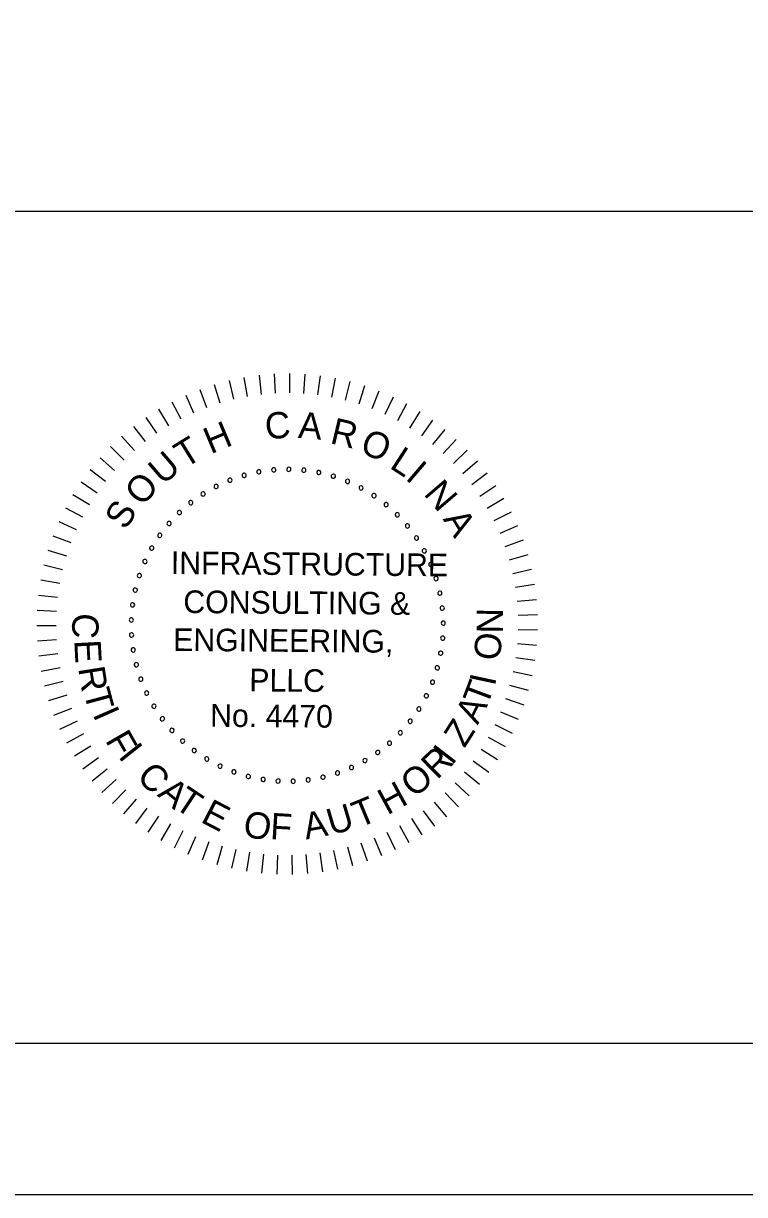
# Model space of a CAD drawing. Extents: x -133.1 to -97, y -1.7 to 20.6.
# Drawn here: x -107.68 to -105.296, y -1.691 to 2.18 of the extents above; entities that cross this region are included whole.
import ezdxf

# ---------------------------------------------------------------- set-up
doc = ezdxf.new("R2010")
doc.units = 0
for name, color, linetype in [('BR_BORDER LINES', 7, 'Continuous'), ('BR_TEXT', 7, 'Continuous'), ('Level 31', 7, 'Continuous')]:
    doc.layers.add(name, color=color, linetype=linetype)

msp = doc.modelspace()

# ---------------------------------------------------------------- linework, layer by layer
at = {"layer": 'BR_BORDER LINES'}
for p, q in [((-110.5071, 1.5591), (-105.1419, 1.5591)), ((-131.3076, -1.191), (-97.6416, -1.191))]:
    msp.add_line(p, q, dxfattribs=at)
at = {"layer": 'BR_TEXT'}
for p, q in [((-106.9512, 1.01), (-106.9401, 0.9473)), ((-106.9012, 1.0172), (-106.894, 0.9539)), ((-106.8509, 1.0213), (-106.8476, 0.9578)), ((-106.8005, 1.0224), (-106.801, 0.9587)), ((-106.75, 1.0204), (-106.7544, 0.9569)), ((-106.6998, 1.0153), (-106.7081, 0.9522)), ((-106.65, 1.0071), (-106.6621, 0.9446)), ((-107.0972, 0.9704), (-107.0749, 0.9107)), ((-107.0494, 0.9866), (-107.0308, 0.9257)), ((-107.0007, 0.9998), (-106.9858, 0.9379)), ((-106.6007, 0.996), (-106.6166, 0.9343)), ((-106.5523, 0.9818), (-106.5719, 0.9213)), ((-107.1895, 0.9295), (-107.1601, 0.873)), ((-107.1439, 0.9513), (-107.1181, 0.8932)), ((-106.5048, 0.9648), (-106.528, 0.9055)), ((-106.4584, 0.9448), (-106.4852, 0.8871)), ((-107.2335, 0.9049), (-107.2008, 0.8503)), ((-106.4133, 0.9221), (-106.4436, 0.8661)), ((-106.3697, 0.8967), (-106.4034, 0.8426)), ((-107.276, 0.8776), (-107.24, 0.8251)), ((-106.3277, 0.8686), (-106.3646, 0.8167)), ((-107.3557, 0.8156), (-107.3135, 0.7679)), ((-107.3168, 0.8478), (-107.2776, 0.7976)), ((-106.2875, 0.8381), (-106.3275, 0.7885)), ((-107.3925, 0.7811), (-107.3475, 0.736)), ((-106.2493, 0.8051), (-106.2922, 0.7581)), ((-107.4272, 0.7444), (-107.3795, 0.7022)), ((-106.2131, 0.7699), (-106.2588, 0.7256)), ((-107.4595, 0.7056), (-107.4094, 0.6664)), ((-106.1791, 0.7326), (-106.2275, 0.6911)), ((-107.4895, 0.665), (-107.437, 0.6289)), ((-106.1475, 0.6932), (-106.1983, 0.6548)), ((-107.5169, 0.6226), (-107.4623, 0.5897)), ((-106.1184, 0.652), (-106.1714, 0.6167)), ((-106.0918, 0.6091), (-106.1469, 0.5771)), ((-107.5416, 0.5786), (-107.4852, 0.5491)), ((-106.0679, 0.5646), (-106.1248, 0.5361)), ((-107.5637, 0.5332), (-107.5055, 0.5072)), ((-106.0467, 0.5188), (-106.1052, 0.4938)), ((-107.5829, 0.4865), (-107.5233, 0.4641)), ((-106.0283, 0.4718), (-106.0883, 0.4504)), ((-107.5992, 0.4387), (-107.5384, 0.42)), ((-107.6126, 0.3901), (-107.5507, 0.3751)), ((-106.0129, 0.4237), (-106.0741, 0.406)), ((-106.0004, 0.3748), (-106.0625, 0.3608)), ((-107.623, 0.3407), (-107.5604, 0.3295)), ((-105.9909, 0.3252), (-106.0538, 0.3151)), ((-107.6304, 0.2907), (-107.5672, 0.2834)), ((-105.9845, 0.2751), (-106.0479, 0.2689)), ((-107.6348, 0.2404), (-107.5712, 0.237)), ((-105.9811, 0.2247), (-106.0448, 0.2224)), ((-107.636, 0.19), (-107.5723, 0.1904)), ((-105.9809, 0.1743), (-106.0445, 0.1758)), ((-107.6342, 0.1395), (-107.5706, 0.1438)), ((-105.9836, 0.1239), (-106.0471, 0.1292)), ((-107.6293, 0.0893), (-107.5661, 0.0974)), ((-105.9895, 0.0737), (-106.0525, 0.0829)), ((-107.6213, 0.0394), (-107.5588, 0.0514)), ((-107.6103, -0.0099), (-107.5487, 0.0059)), ((-105.9984, 0.024), (-106.0607, 0.0371)), ((-106.0103, -0.025), (-106.0717, -0.0082)), ((-107.5964, -0.0584), (-107.5358, -0.0388)), ((-106.0252, -0.0733), (-106.0855, -0.0527)), ((-107.5795, -0.106), (-107.5202, -0.0828)), ((-106.043, -0.1205), (-106.1019, -0.0963)), ((-107.5597, -0.1524), (-107.5019, -0.1256)), ((-106.0636, -0.1666), (-106.1209, -0.1389)), ((-107.5371, -0.1976), (-107.4811, -0.1673)), ((-106.087, -0.2113), (-106.1426, -0.1802)), ((-107.5119, -0.2413), (-107.4578, -0.2077)), ((-106.1131, -0.2545), (-106.1667, -0.22)), ((-107.484, -0.2834), (-107.4321, -0.2465)), ((-106.1418, -0.2961), (-106.1931, -0.2584)), ((-107.4536, -0.3237), (-107.404, -0.2837)), ((-106.173, -0.3358), (-106.2219, -0.2951)), ((-107.4208, -0.362), (-107.3737, -0.3191)), ((-106.2065, -0.3735), (-106.2529, -0.3299)), ((-107.3857, -0.3983), (-107.3413, -0.3527)), ((-107.3485, -0.4324), (-107.307, -0.3841)), ((-106.2423, -0.4092), (-106.2859, -0.3628)), ((-107.3092, -0.4642), (-107.2708, -0.4135)), ((-106.32, -0.4736), (-106.3576, -0.4222)), ((-106.2801, -0.4426), (-106.3208, -0.3936)), ((-107.2681, -0.4935), (-107.2328, -0.4405)), ((-106.3616, -0.5021), (-106.3961, -0.4485)), ((-107.2253, -0.5203), (-107.1933, -0.4652)), ((-107.1809, -0.5444), (-107.1523, -0.4875)), ((-106.4498, -0.5513), (-106.4774, -0.4939)), ((-106.4049, -0.528), (-106.436, -0.4725)), ((-107.1352, -0.5657), (-107.1101, -0.5072)), ((-107.0882, -0.5842), (-107.0668, -0.5243)), ((-107.0402, -0.5998), (-107.0225, -0.5387)), ((-106.5432, -0.5894), (-106.5637, -0.5291)), ((-106.4959, -0.5718), (-106.52, -0.5128)), ((-106.9913, -0.6125), (-106.9773, -0.5504)), ((-106.9418, -0.6221), (-106.9316, -0.5593)), ((-106.8918, -0.6288), (-106.8854, -0.5654)), ((-106.8414, -0.6323), (-106.8389, -0.5687)), ((-106.7909, -0.6328), (-106.7923, -0.5691)), ((-106.7405, -0.6302), (-106.7458, -0.5667)), ((-106.6903, -0.6245), (-106.6995, -0.5615)), ((-106.6406, -0.6158), (-106.6536, -0.5535)), ((-106.5915, -0.6041), (-106.6083, -0.5427))]:
    msp.add_line(p, q, dxfattribs=at)
for centre, start, end in [((-106.9021, 0.6977), 10.6038, 190.6038), ((-106.9021, 0.6977), 190.6038, 10.6038), ((-106.8527, 0.7043), 5.0653, 185.0653), ((-106.8527, 0.7043), 185.0653, 5.0653), ((-106.8029, 0.7062), 359.5268, 179.5268), ((-106.8029, 0.7062), 179.5268, 359.5268), ((-106.7531, 0.7033), 173.9884, 353.9884), ((-106.7531, 0.7033), 353.9884, 173.9884), ((-106.7039, 0.6956), 168.4499, 348.4499), ((-106.7039, 0.6956), 348.4499, 168.4499), ((-106.9977, 0.6702), 21.6807, 201.6807), ((-106.9977, 0.6702), 201.6807, 21.6807), ((-106.9506, 0.6862), 16.1422, 196.1422), ((-106.9506, 0.6862), 196.1422, 16.1422), ((-106.6557, 0.6832), 162.9114, 342.9114), ((-106.6557, 0.6832), 342.9114, 162.9114), ((-106.6088, 0.6662), 157.373, 337.373), ((-106.6088, 0.6662), 337.373, 157.373), ((-107.0864, 0.6248), 32.7576, 212.7576), ((-107.0864, 0.6248), 212.7576, 32.7576), ((-107.0431, 0.6496), 27.2191, 207.2191), ((-107.0431, 0.6496), 207.2191, 27.2191), ((-106.5639, 0.6447), 151.8345, 331.8345), ((-106.5639, 0.6447), 331.8345, 151.8345), ((-106.5212, 0.619), 146.2961, 326.2961), ((-106.5212, 0.619), 326.2961, 146.2961), ((-107.127, 0.5959), 38.2961, 218.2961), ((-107.127, 0.5959), 218.2961, 38.2961), ((-106.4811, 0.5893), 140.7576, 320.7576), ((-106.4811, 0.5893), 320.7576, 140.7576), ((-107.1646, 0.5633), 43.8345, 223.8345), ((-107.1646, 0.5633), 223.8345, 43.8345), ((-106.4442, 0.5559), 135.2191, 315.2191), ((-106.4442, 0.5559), 315.2191, 135.2191), ((-107.1989, 0.5271), 49.373, 229.373), ((-107.1989, 0.5271), 229.373, 49.373), ((-106.4106, 0.5191), 129.6807, 309.6807), ((-106.4106, 0.5191), 309.6807, 129.6807), ((-107.2296, 0.4879), 54.9114, 234.9114), ((-107.2296, 0.4879), 234.9114, 54.9114), ((-106.3808, 0.4792), 124.1422, 304.1422), ((-106.3808, 0.4792), 304.1422, 124.1422), ((-107.2563, 0.4458), 60.4499, 240.4499), ((-107.2563, 0.4458), 240.4499, 60.4499), ((-106.3549, 0.4366), 118.6038, 298.6038), ((-106.3549, 0.4366), 298.6038, 118.6038), ((-107.2788, 0.4014), 65.9884, 245.9884), ((-107.2788, 0.4014), 245.9884, 65.9884), ((-106.3333, 0.3917), 113.0653, 293.0653), ((-106.3333, 0.3917), 293.0653, 113.0653), ((-107.297, 0.3549), 71.5268, 251.5268), ((-107.297, 0.3549), 251.5268, 71.5268), ((-106.3161, 0.3449), 107.5268, 287.5268), ((-106.3161, 0.3449), 287.5268, 107.5268), ((-107.3106, 0.307), 77.0653, 257.0653), ((-107.3106, 0.307), 257.0653, 77.0653), ((-106.3035, 0.2967), 101.9884, 281.9884), ((-106.3035, 0.2967), 281.9884, 101.9884), ((-107.3195, 0.258), 82.6038, 262.6038), ((-107.3195, 0.258), 262.6038, 82.6038), ((-106.2956, 0.2475), 96.4499, 276.4499), ((-106.2956, 0.2475), 276.4499, 96.4499), ((-107.3236, 0.2083), 88.1422, 268.1422), ((-107.3236, 0.2083), 268.1422, 88.1422), ((-106.2925, 0.1977), 90.9114, 270.9114), ((-106.2925, 0.1977), 270.9114, 90.9114), ((-107.3229, 0.1585), 93.6807, 273.6807), ((-107.3229, 0.1585), 273.6807, 93.6807), ((-106.2942, 0.1479), 85.373, 265.373), ((-106.2942, 0.1479), 265.373, 85.373), ((-107.3174, 0.109), 99.2191, 279.2191), ((-107.3174, 0.109), 279.2191, 99.2191), ((-106.3007, 0.0985), 79.8345, 259.8345), ((-106.3007, 0.0985), 259.8345, 79.8345), ((-107.3071, 0.0602), 104.7576, 284.7576), ((-107.3071, 0.0602), 284.7576, 104.7576), ((-106.312, 0.05), 74.2961, 254.2961), ((-106.312, 0.05), 254.2961, 74.2961), ((-107.2922, 0.0126), 110.2961, 290.2961), ((-107.2922, 0.0126), 290.2961, 110.2961), ((-106.3279, 0.0028), 68.7576, 248.7576), ((-106.3279, 0.0028), 248.7576, 68.7576), ((-107.2728, -0.0332), 115.8345, 295.8345), ((-107.2728, -0.0332), 295.8345, 115.8345), ((-106.3483, -0.0427), 63.2191, 243.2191), ((-106.3483, -0.0427), 243.2191, 63.2191), ((-107.249, -0.077), 121.373, 301.373), ((-107.249, -0.077), 301.373, 121.373), ((-107.2211, -0.1183), 126.9114, 306.9114), ((-107.2211, -0.1183), 306.9114, 126.9114), ((-106.3729, -0.086), 57.6807, 237.6807), ((-106.3729, -0.086), 237.6807, 57.6807), ((-107.1894, -0.1567), 132.4499, 312.4499), ((-107.1894, -0.1567), 312.4499, 132.4499), ((-106.4016, -0.1267), 52.1422, 232.1422), ((-106.4016, -0.1267), 232.1422, 52.1422), ((-107.1541, -0.1919), 137.9884, 317.9884), ((-107.1541, -0.1919), 317.9884, 137.9884), ((-106.4702, -0.1989), 41.0653, 221.0653), ((-106.4342, -0.1645), 46.6038, 226.6038), ((-106.4342, -0.1645), 226.6038, 46.6038), ((-107.1156, -0.2235), 143.5268, 323.5268), ((-107.1156, -0.2235), 323.5268, 143.5268), ((-106.5093, -0.2297), 35.5268, 215.5268), ((-106.5093, -0.2297), 215.5268, 35.5268), ((-106.4702, -0.1989), 221.0653, 41.0653), ((-107.0742, -0.2512), 149.0653, 329.0653), ((-107.0742, -0.2512), 329.0653, 149.0653), ((-107.0303, -0.2749), 334.6038, 154.6038), ((-106.5513, -0.2566), 29.9884, 209.9884), ((-106.5513, -0.2566), 209.9884, 29.9884), ((-107.0303, -0.2749), 154.6038, 334.6038), ((-106.9843, -0.2941), 160.1422, 340.1422), ((-106.9843, -0.2941), 340.1422, 160.1422), ((-106.9367, -0.3089), 165.6807, 345.6807), ((-106.9367, -0.3089), 345.6807, 165.6807), ((-106.6899, -0.3114), 13.373, 193.373), ((-106.642, -0.2976), 18.9114, 198.9114), ((-106.642, -0.2976), 198.9114, 18.9114), ((-106.5957, -0.2793), 24.4499, 204.4499), ((-106.5957, -0.2793), 204.4499, 24.4499), ((-106.8879, -0.3189), 171.2191, 351.2191), ((-106.8879, -0.3189), 351.2191, 171.2191), ((-106.8384, -0.3242), 356.7576, 176.7576), ((-106.8384, -0.3242), 176.7576, 356.7576), ((-106.7885, -0.3248), 2.2961, 182.2961), ((-106.7885, -0.3248), 182.2961, 2.2961), ((-106.7389, -0.3205), 7.8345, 187.8345), ((-106.7389, -0.3205), 187.8345, 7.8345), ((-106.6899, -0.3114), 193.373, 13.373)]:
    msp.add_arc(centre, 0.00701, start, end, dxfattribs=at)
at = {"layer": 'Level 31'}
msp.add_lwpolyline([(-133.1409, -1.691), (-97.141, -1.691), (-97.141, 20.309), (-133.1409, 20.309)], close=True, dxfattribs=at)

# ---------------------------------------------------------------- texts
at = {"layer": 'BR_TEXT'}
for s, height, rotation, p in [('C', 0.0872, 4.7281, (-106.8784, 0.8048)), ('A', 0.0872, 355.6981, (-106.7739, 0.8098)), ('H', 0.0872, 22.7882, (-107.0612, 0.7554)), ('R', 0.0872, 346.6681, (-106.6696, 0.7928)), ('T', 0.0872, 31.8182, (-107.1461, 0.7078)), ('O', 0.0872, 337.638, (-106.5719, 0.763)), ('L', 0.0872, 327.108, (-106.4731, 0.7125)), ('U', 0.0872, 40.8482, (-107.2194, 0.6516)), ('I', 0.0872, 319.578, (-106.4205, 0.6747)), ('O', 0.0872, 49.8782, (-107.2864, 0.5806)), ('N', 0.0872, 310.548, (-106.3597, 0.6239)), ('S', 0.0872, 58.9083, (-107.3418, 0.5024)), ('A', 0.0872, 301.5179, (-106.2946, 0.5415)), ('INFRASTRUCTURE', 0.074771, 359.5268, (-107.1932, 0.3599)), ('CONSULTING &', 0.074771, 359.5268, (-107.1519, 0.2313)), ('N', 0.0872, 89.2085, (-106.0953, 0.1628)), ('C', 0.0872, 267.025, (-107.5168, 0.2325)), ('ENGINEERING,', 0.074771, 359.5268, (-107.1855, 0.1059)), ('O', 0.0872, 83.2085, (-106.1064, 0.0713)), ('E', 0.0872, 273.025, (-107.5124, 0.1409)), ('R', 0.0872, 279.025, (-107.4996, 0.0487)), ('PLLC', 0.07477, 359.5268, (-106.9338, -0.0277)), ('T', 0.0872, 69.3954, (-106.1476, -0.0805)), ('I', 0.0872, 77.9093, (-106.1219, -0.013)), ('T', 0.0872, 285.025, (-107.4822, -0.0301)), ('No. 4470', 0.07477, 359.5268, (-107.0633, -0.1446)), ('A', 0.0872, 63.3954, (-106.1784, -0.1408)), ('I', 0.0872, 293.7713, (-107.4525, -0.1032)), ('Z', 0.0872, 57.3954, (-106.2222, -0.2172)), ('F', 0.0872, 299.7713, (-107.4113, -0.1893)), ('I', 0.0872, 308.5268, (-107.3692, -0.2431)), ('R', 0.0872, 44.5268, (-106.3127, -0.3221)), ('I', 0.0872, 52.3339, (-106.2633, -0.2748)), ('C', 0.0872, 314.5268, (-107.3099, -0.3133)), ('O', 0.0872, 38.5268, (-106.3893, -0.3821)), ('A', 0.0872, 320.5268, (-107.2407, -0.3718)), ('T', 0.0872, 326.5268, (-107.1863, -0.4103)), ('H', 0.0872, 28.5268, (-106.4774, -0.4381)), ('E', 0.0872, 332.5268, (-107.0977, -0.4581)), ('T', 0.0872, 22.5268, (-106.5706, -0.4799)), ('O', 0.0872, 350.5268, (-106.9576, -0.507)), ('A', 0.0872, 10.5268, (-106.7462, -0.5177)), ('U', 0.0872, 16.5268, (-106.6623, -0.5042)), ('F', 0.0872, 356.5268, (-106.8661, -0.5161))]:
    msp.add_text(s, height=height, rotation=rotation, dxfattribs=at).set_placement(p)

doc.saveas('drawing.dxf')
